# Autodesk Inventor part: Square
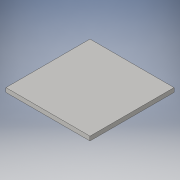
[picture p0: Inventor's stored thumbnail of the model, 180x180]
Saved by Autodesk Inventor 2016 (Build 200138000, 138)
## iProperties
Created: 2017-06
Part Number: Square
Material: Glass
Document SubType Name: Modeling
Designer: agnim
Density: 2.18 g/cm^3
Appearance: Clear
Author: agnim
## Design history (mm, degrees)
sketch "Sketch1"
  geometry: L1 (0, 0)-(25.4, 0); L2 (25.4, 0)-(25.4, -25.4); L3 (25.4, -25.4)-(0, -25.4); L4 (0, -25.4)-(0, 0)
  constraints: 8 end point, 2 parallel, 1 horizontal, 1 perpendicular
  dimensions: "d0" = 25.4 distance of L2.end L3.end; "d1" = 25.4 distance of L1.end L2.end
extrude "Extrusion1" new body sketch "Sketch1" distance "d2" = 1.27; taper "d3" = 0 deg
body "Solid1"
